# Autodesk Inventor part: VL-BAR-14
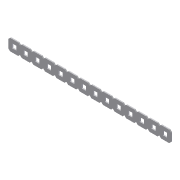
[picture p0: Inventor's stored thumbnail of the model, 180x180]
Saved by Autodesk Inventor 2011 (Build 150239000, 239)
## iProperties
Created: 2005-08
Part Number: VL-BAR-14
Document SubType Name: Sheet Metal
Density: 1 g/cm^3
Mass: 2.36703 g
Surface Area: 45.8308 cm^2
Volume: 2.36703 cm^3
Sheet Metal Rule: Default
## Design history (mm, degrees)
node "Face1"
  sketch "Sketch1"
    geometry: L1 (-15.07, 9.738)-(-23.96, 9.738); L2 (-25.865, 7.833)-(-25.865, -1.057); L3 (-23.96, -2.962)-(-15.07, -2.962); L4 (-13.165, -1.057)-(-13.165, 7.833); L5 (-25.865, 7.833)-(-23.96, 9.738); L6 (-25.865, -1.057)-(-23.96, -2.962); L7 (-15.07, -2.962)-(-13.165, -1.057); L8 (-13.165, 7.833)-(-15.07, 9.738); L9 (-21.801, 5.674)-(-17.229, 5.674); L10 (-17.229, 5.674)-(-17.229, 1.102); L11 (-17.229, 1.102)-(-21.801, 1.102); L12 (-21.801, 1.102)-(-21.801, 5.674); 4 further points
    constraints: 24 end point, 8 point on line, 4 parallel, 2 horizontal, 2 perpendicular
    dimensions: "d0" = 12.7 distance of point (-25.865, 9.738) point (-25.865, -2.962); "d1" = 12.7 distance of point (-13.165, 9.738) point (-25.865, 9.738); "d2" = 1.905 distance of L2.start point (-25.865, 9.738); "d3" = 1.905 distance of L1.end point (-25.865, 9.738) (= d2); "d4" = 1.905 distance of L2.end point (-25.865, -2.962) (= d2); "d5" = 1.905 distance of L3.start point (-25.865, -2.962) (= d4); "d6" = 1.905 distance of L3.end point (-13.165, -2.962) (= d2); "d7" = 1.905 distance of L4.start point (-13.165, -2.962) (= d6); "d8" = 1.905 distance of L4.end point (-13.165, 9.738) (= d2); "d9" = 1.905 distance of L1.start point (-13.165, 9.738) (= d8); "d10" = 4.572 distance of L11.end L9.start; "d11" = 4.572 distance of L10.end L11.end; "d12" = 4.064 distance between parallel lines of L1 L9; "d13" = 4.064 distance between parallel lines of L4 L10
pattern_linear "Rectangular Pattern1" dims "d17" = 12.7
sketch "Sketch2"
  geometry: L1 (171.831, -4.064)-(171.831, -8.636) reference; L2 (171.831, -8.636)-(167.259, -8.636) reference; L3 (167.259, -8.636)-(167.259, -4.064) reference; L4 (167.259, -4.064)-(171.831, -4.064) reference; L5 (159.131, -4.064)-(159.131, -8.636) reference; L6 (159.131, -8.636)-(154.559, -8.636) reference; L7 (154.559, -8.636)-(154.559, -4.064) reference; L8 (154.559, -4.064)-(159.131, -4.064) reference; L9 (146.431, -4.064)-(146.431, -8.636) reference; L10 (146.431, -8.636)-(141.859, -8.636) reference; L11 (141.859, -8.636)-(141.859, -4.064) reference; L12 (141.859, -4.064)-(146.431, -4.064) reference; L13 (133.731, -4.064)-(133.731, -8.636) reference; L14 (133.731, -8.636)-(129.159, -8.636) reference; L15 (129.159, -8.636)-(129.159, -4.064) reference; L16 (129.159, -4.064)-(133.731, -4.064) reference; L17 (121.031, -4.064)-(121.031, -8.636) reference; L18 (121.031, -8.636)-(116.459, -8.636) reference; L19 (116.459, -8.636)-(116.459, -4.064) reference; L20 (116.459, -4.064)-(121.031, -4.064) reference; L21 (108.331, -4.064)-(108.331, -8.636) reference; L22 (108.331, -8.636)-(103.759, -8.636) reference; L23 (103.759, -8.636)-(103.759, -4.064) reference; L24 (103.759, -4.064)-(108.331, -4.064) reference; L25 (95.631, -4.064)-(95.631, -8.636) reference; L26 (95.631, -8.636)-(91.059, -8.636) reference; L27 (91.059, -8.636)-(91.059, -4.064) reference; L28 (91.059, -4.064)-(95.631, -4.064) reference; L29 (82.931, -4.064)-(82.931, -8.636) reference; L30 (82.931, -8.636)-(78.359, -8.636) reference; L31 (78.359, -8.636)-(78.359, -4.064) reference; L32 (78.359, -4.064)-(82.931, -4.064) reference; L33 (70.231, -4.064)-(70.231, -8.636) reference; L34 (70.231, -8.636)-(65.659, -8.636) reference; L35 (65.659, -8.636)-(65.659, -4.064) reference; L36 (65.659, -4.064)-(70.231, -4.064) reference; L37 (57.531, -4.064)-(57.531, -8.636) reference; L38 (57.531, -8.636)-(52.959, -8.636) reference; L39 (52.959, -8.636)-(52.959, -4.064) reference; L40 (52.959, -4.064)-(57.531, -4.064) reference; L41 (44.831, -4.064)-(44.831, -8.636) reference; L42 (44.831, -8.636)-(40.259, -8.636) reference; L43 (40.259, -8.636)-(40.259, -4.064) reference; L44 (40.259, -4.064)-(44.831, -4.064) reference; L45 (32.131, -4.064)-(32.131, -8.636) reference; L46 (32.131, -8.636)-(27.559, -8.636) reference; L47 (27.559, -8.636)-(27.559, -4.064) reference; L48 (27.559, -4.064)-(32.131, -4.064) reference; L49 (19.431, -4.064)-(19.431, -8.636) reference; L50 (19.431, -8.636)-(14.859, -8.636) reference; L51 (14.859, -8.636)-(14.859, -4.064) reference; L52 (14.859, -4.064)-(19.431, -4.064) reference; L53 (6.731, -4.064)-(6.731, -8.636) reference; L54 (6.731, -8.636)-(2.159, -8.636) reference; L55 (2.159, -8.636)-(2.159, -4.064) reference; L56 (2.159, -4.064)-(6.731, -4.064) reference; L57 (0, 0)-(8.89, 0) reference; L58 (-1.905, -1.905)-(0, 0) reference; L59 (-1.905, -10.795)-(-1.905, -1.905) reference; L60 (0, -12.7)-(-1.905, -10.795) reference; L61 (8.89, -12.7)-(0, -12.7) reference; L62 (10.795, -10.795)-(8.89, -12.7) reference; L63 (12.7, -12.7)-(10.795, -10.795) reference; L64 (21.59, -12.7)-(12.7, -12.7) reference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; C1 r 2.286 at (4.445, -6.35); C2 r 2.286 at (169.545, -6.35)
  constraints: 8 tangent, 2 centre point
body "Solid1"
face "Plate1" dims "Thickness" = 1.27
other parameters: "BendRadius" = 1.27 (= Thickness), "BendReliefWidth" = 1.27 (= Thickness), "BendReliefDepth" = 0.635 (= 0.5 x Thickness), "CornerReliefSize" = 5.08 (= 4 x Thickness), "SeamGap" = 0.00508, "MinimumRemnant" = 2.54 (= 2 x Thickness), "TransitionRadius" = 1.27 (= BendRadius), "d14" = 1.27 (= BendRadius), "JacobiRadiusSize" = 1.27 (= Thickness), "GapSize" = 1.27 (= Thickness)
